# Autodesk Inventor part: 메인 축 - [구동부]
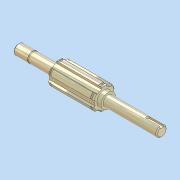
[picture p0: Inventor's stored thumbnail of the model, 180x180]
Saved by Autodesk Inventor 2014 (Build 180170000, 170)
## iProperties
Created: 2012-05
Part Number: 메인 축 - [구동부]
Document SubType Name: 모델링
Designer: SeoGD™
Mass: 168.566 g
Surface Area: 72.5104 cm^2
Volume: 21.4461 cm^3
Density: 7.86 g/cm^3
Material: 강철, 연강
Appearance: 강철
변환 표준: STEP AP214IS
파일 이름: C:\Users\SeoGD\Desktop\?쒗뿕\硫붿씤 異?.stp
전처리기: Build: 253, Release: 2010 SP1 - Date: Wed 07/29/2009
전송 단위: 밀리미터
불확실성: 0.01
Author: SeoGD™
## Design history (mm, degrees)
sketch "스케치1"
  geometry: L1 (-69.5, 0)-(69.5, 0); L2 (69.5, 0)-(69.5, 5); L3 (69.5, 5)-(55.5, 5); L4 (55.5, 5)-(55.5, 4.8); L5 (55.5, 4.8)-(54.35, 4.8); L6 (54.35, 4.8)-(54.35, 5); L7 (54.35, 5)-(30.5, 5); L8 (30.5, 5)-(30.5, 9); L9 (30.5, 9)-(-13.5, 9); L10 (-13.5, 9)-(-13.5, 7); L11 (-13.5, 7)-(-17.5, 7); L12 (-17.5, 7)-(-17.5, 5); L13 (-17.5, 5)-(-69.5, 5); L14 (-69.5, 5)-(-69.5, 0); 2 further points
  constraints: 28 end point, 9 parallel, 4 collinear, 2 perpendicular, 1 coincident, 1 horizontal, 1 midpoint
  dimensions: "d2" = 1.15 distance between parallel lines of L6 L4; "d3" = 10 diameter of L3 L1; "d4" = 9.6 diameter of L5 L1; "d6" = 44 distance between parallel lines of L10 L8; "d7" = 4 distance between parallel lines of L12 L10; "d8" = 14 diameter of L11 L1; "d9" = 18 diameter of L9 L1; "d33" = 52 distance from line of L12.end L14; "d37" = 39 distance between parallel lines of L8 L2; "d38" = 14 distance between parallel lines of L2 L4
revolve "회전1" sketch "스케치1" stored, may be unused: angle "d10" = 90 deg
sketch "스케치2"
  geometry: L1 (2.5, 10.712)-(2.5, 8.646); L2 (-2.5, 10.712)-(-2.5, 8.646); A1 r 9 centre (0, 0) between (2.5, 8.646) and (-2.5, 8.646) reference; A2 r 11 centre (0, 0) between (2.5, 10.712) and (-2.5, 10.712); 1 further point
  constraints: 4 end point, 4 point on circle, 2 parallel, 1 centre point, 1 coincident, 1 vertical
  dimensions: "d11" = 22 diameter of A2; "d12" = 5 distance between parallel lines of L1 L2
extrude "돌출1" join sketch "스케치2" stored distance "d13" = 10; taper "d14" = 0 deg
chamfer "모따기1" distance "d15" = 1; stored, may be unused: second distance "d16" = 2, angle "d17" = 45 deg
node "작업 평면1"
node "작업 평면2"
sketch "스케치3"
  geometry: L1 (2.5, 10.712)-(2.5, 10.198); L2 (-2.5, 10.712)-(-2.5, 10.198); A1 r 11 centre (0, 0) between (2.5, 10.712) and (-2.5, 10.712) reference; A2 r 10.5 centre (0, 0) between (2.5, 10.198) and (-2.5, 10.198); 1 further point
  constraints: 4 end point, 2 point on circle, 1 centre point, 1 coincident, 1 parallel, 1 vertical
  dimensions: "d19" = 21 diameter of A2
extrude "돌출2" cut sketch "스케치3" distance "d20" = 1.35; taper "d21" = 0 deg
node "작업 평면3"
sketch "스케치4"
  geometry: L1 (-26, -5)-(-26, 5) reference; L2 (-26, 1.5)-(-12.5, 1.5); L3 (-12.5, -1.5)-(-26, -1.5); A1 r 1.5 centre (-12.5, 0) between (-12.5, -1.5) and (-12.5, 1.5); 2 further points
  constraints: 4 end point, 2 perpendicular, 2 point on circle, 2 point on line, 2 tangent, 1 centre point, 1 horizontal alignment, 1 midpoint
  dimensions: "d25" = 3 distance between parallel lines of L3 L2; "d26" = 15 dimension on A1 L1
extrude "돌출3" cut sketch "스케치4" distance "d27" = 1.8; taper "d28" = 0 deg
chamfer "모따기2" distance "d29" = 1; stored, may be unused: second distance "d30" = 2, angle "d31" = 45 deg
node "솔리드1"
node "솔리드 본체"
node "곡면 본체"
mirror "대칭1"
pattern_circular "원형 패턴1" dims "d23" = 360 deg
node "솔리드2"
other parameters: "d18" = -1.65
